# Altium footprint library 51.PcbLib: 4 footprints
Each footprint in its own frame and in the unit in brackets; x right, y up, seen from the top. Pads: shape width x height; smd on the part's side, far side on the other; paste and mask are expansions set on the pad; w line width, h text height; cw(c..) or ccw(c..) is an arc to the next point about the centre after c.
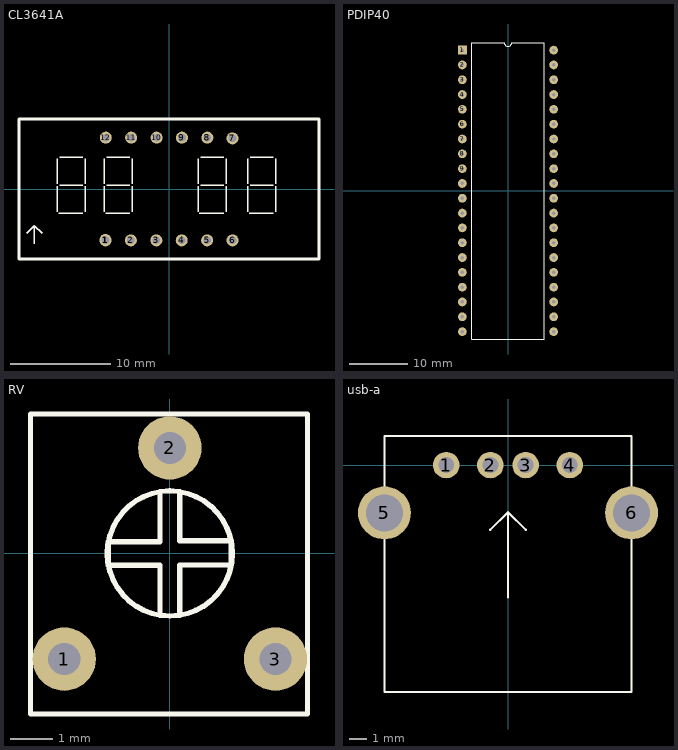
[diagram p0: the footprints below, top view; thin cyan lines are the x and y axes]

## CL3641A [mm]
pads (14):
  round 1.2 hole 0.65: 1(-6.352,-5.101)
  round 1.2 hole 0.762: 1(-6.348,-5.132) 1(-6.348,-5.132) 2(-3.808,-5.132) 3(-1.268,-5.132) 4(1.272,-5.132) 5(3.812,-5.132) 6(6.352,-5.132) 7(6.348,5.059) 8(3.837,5.132) 9(1.297,5.132) 10(-1.243,5.132) 11(-3.783,5.132) 12(-6.323,5.132)
Top Overlay:
  lines w0.127: -14.224,-4.445 -13.462,-3.683 ; -13.462,-5.461 -13.462,-3.683 ; -11.176,-2.286 -11.176,0.254 ; -11.176,0.508 -11.176,3.048 ; -11.049,-2.413 -8.636,-2.413 ; -10.922,0.381 -8.636,0.381 ; -10.922,3.175 -8.636,3.175 ; -8.382,-2.286 -8.382,0.254 ; -8.382,0.508 -8.382,3.048 ; -6.477,-2.286 -6.477,0.254 ; -6.477,0.508 -6.477,3.048 ; -6.35,-2.413 -3.937,-2.413 ; -6.223,0.381 -3.937,0.381 ; -6.223,3.175 -3.937,3.175 ; -3.683,-2.286 -3.683,0.254 ; -3.683,0.508 -3.683,3.048 ; 2.921,-2.286 2.921,0.254 ; 2.921,0.508 2.921,3.048 ; 3.048,-2.413 5.461,-2.413 ; 3.175,0.381 5.461,0.381 ; 3.175,3.175 5.461,3.175 ; 5.715,-2.286 5.715,0.254 ; 5.715,0.508 5.715,3.048 ; 7.874,-2.286 7.874,0.254 ; 7.874,0.508 7.874,3.048 ; 8.001,-2.413 10.414,-2.413 ; 8.128,0.381 10.414,0.381 ; 8.128,3.175 10.414,3.175 ; 10.668,-2.286 10.668,0.254 ; 10.668,0.508 10.668,3.048 ; -13.462,-3.683 -12.7,-4.445 -13.462,-3.683
  lines w0.254: -15,-7 15,-7 15,7 -15,7 -15,-7
3D body "数码管4连.STEP": height 2, standoff -11.2, extent -14.732,-7.254 15.268,6.746

## PDIP40 [mm]
pads (40):
  rect 1.5x1.5 hole 0.6: 1(-7.82,24.13)
  round 1.5 hole 0.6: 2(-7.82,21.59) 3(-7.82,19.05) 4(-7.82,16.51) 5(-7.82,13.97) 6(-7.82,11.43) 7(-7.82,8.89) 8(-7.82,6.35) 9(-7.82,3.81) 10(-7.82,1.27) 11(-7.82,-1.27) 12(-7.82,-3.81) 13(-7.82,-6.35) 14(-7.82,-8.89) 15(-7.82,-11.43) 16(-7.82,-13.97) 17(-7.82,-16.51) 18(-7.82,-19.05) 19(-7.82,-21.59) 20(-7.82,-24.13) 21(7.82,-24.13) 22(7.82,-21.59) 23(7.82,-19.05) 24(7.82,-16.51) 25(7.82,-13.97) 26(7.82,-11.43) 27(7.82,-8.89) 28(7.82,-6.35) 29(7.82,-3.81) 30(7.82,-1.27) 31(7.82,1.27) 32(7.82,3.81) 33(7.82,6.35) 34(7.82,8.89) 35(7.82,11.43) 36(7.82,13.97) 37(7.82,16.51) 38(7.82,19.05) 39(7.82,21.59) 40(7.82,24.13)
Top Overlay:
  lines w0.2: -6.235,-25.4 -6.235,25.4 -0.635,25.4 ccw(c0,25.4) 0.635,25.4 6.235,25.4 6.235,-25.4 -6.235,-25.4
3D body "DIP40-600.step": height 5.7, standoff -2.58, extent -7.872,-26.225 7.618,26.225

## RV [mm]
pads (3):
  round 1.5 hole 0.762: 1(-2.5,-2.5) 2(0,2.5) 3(2.5,-2.5)
Top Overlay:
  circle w0.127: c0,0 r1.481
  lines w0.127: -0.232,-1.463 -0.232,-0.276 -1.455,-0.276 -1.455,0.276 -0.232,0.276 -0.232,1.463 ; 0.232,-1.463 0.232,-0.271 1.451,-0.271 1.451,0.298 0.232,0.298 0.232,1.463 ; -3.3,-3.8 -1.462,-3.8 1.82,-3.8 2.65,-3.8 3.26,-3.8 3.26,3.302 2.557,3.302 2.344,3.302 1.343,3.302 0.708,3.302 -0.561,3.302 -1.196,3.302 -2.815,3.302 -3.3,3.302 -3.3,-3.8
3D body "PA0630NOXOX-HA1.STEP": height 7.5, standoff -2, extent -3.2,-3.8 3.2,3.2

## usb-a [mm] "2"
pads (6):
  round 1.5 hole 0.9: 1(-3.5,0) 2(-1,0) 3(1,0) 4(3.5,0)
  round 3 hole 2.1: 5(-7,-2.71) 6(7,-2.71)
Top Overlay:
  lines w0.127: -7,-2.71 -7,-12.845 -6.985,-12.86 7,-12.86 7,-2.71 ; -7,-1.21 -7,1.651 -2.597,1.651 -1.298,1.651 1.301,1.651 2.6,1.651 7,1.651 7,-3.167 ; -3.302,-12.86 4.953,-12.86 ; 1,-3.667 0,-2.667 ; 0,-2.667 -1,-3.667 0,-2.667 ; 0,-2.667 0,-7.493 0,-2.667
3D body "USB-A-S-F-B-TH.step": height 8.85, standoff -2.07, extent -7.9,-13.127 7.899,0.973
